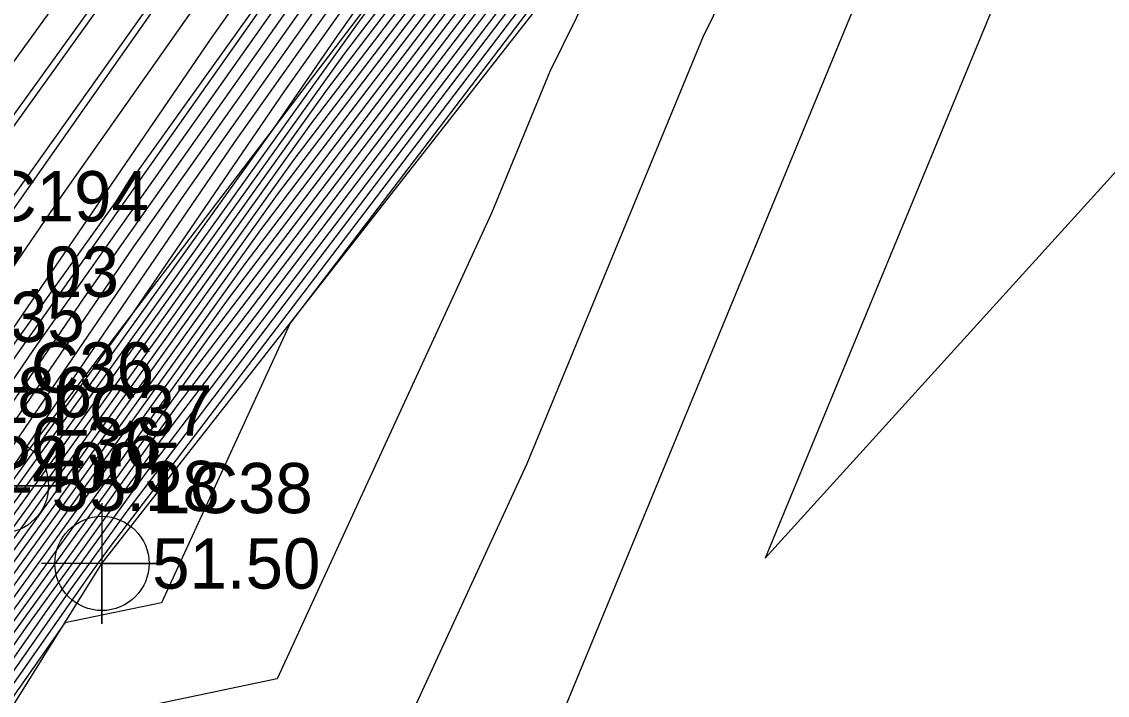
# Model space of a CAD drawing. Extents: x 2188792 to 2191981, y 386090 to 389710.
# Drawn here: x 2190065.7 to 2190119.7, y 387465.7 to 387499.2 of the extents above; entities that cross this region are included whole.
import ezdxf

# ---------------------------------------------------------------- set-up
doc = ezdxf.new("R2010")
doc.units = 0
for name, color, linetype in [('DTM Contours Major', 7, 'Continuous'), ('DTM Contours Minor', 7, 'Continuous'), ('Exist DTM Breakline', 7, 'Continuous'), ('Exist DTM Breakline Cogo Comment', 7, 'Continuous'), ('Exist DTM Breakline Cogo Elevation', 7, 'Continuous'), ('Exist DTM Breakline Cogo Number', 7, 'Continuous'), ('Exist DTM Breakline Cogo Point CELL', 7, 'Continuous'), ('Exist Roads EOP', 7, 'Continuous'), ('Exist Roads EOP Cogo Elevation', 7, 'Continuous'), ('Exist Roads EOP Cogo Number', 7, 'Continuous'), ('Exist Roads EOT', 7, 'Continuous')]:
    doc.layers.add(name, color=color, linetype=linetype)

msp = doc.modelspace()

# ---------------------------------------------------------------- linework, layer by layer
at = {"layer": 'DTM Contours Major'}
for points in [[(2189985.275, 387383.669), (2189994.24, 387397.334), (2190000.542, 387406.584), (2190005.068, 387412.932), (2190013.175, 387425.126), (2190018.833, 387434.036), (2190019.851, 387435.22), (2190023.561, 387439.509), (2190030.225, 387447.562), (2190040.144, 387460.464), (2190042.779, 387463.794), (2190047.272, 387469.736), (2190059.404, 387485.693), (2190062.073, 387489.527), (2190073.957, 387506.082), (2190075.657, 387508.517), (2190091.037, 387529.933), (2190091.267, 387530.33), (2190091.329, 387530.517), (2190091.393, 387530.607), (2190108.388, 387554.062)], [(2190106.731, 387542.448), (2190099.469, 387532.426), (2190096.508, 387528.215), (2190094.775, 387523.014), (2190093.569, 387521.301), (2190083.683, 387507.247), (2190079.859, 387502.134), (2190066.248, 387482.85), (2190062.633, 387477.566), (2190059.105, 387472.827), (2190048.491, 387458.326), (2190044.873, 387453.452), (2190030.711, 387434.1), (2190030.018, 387433.137), (2190027.341, 387429.417), (2190023.779, 387424.466), (2190009.82, 387405.068), (2190006.105, 387399.906), (2189992.299, 387380.721)], [(2190110.745, 387540.41), (2190105.891, 387533.526), (2190105.582, 387533.077), (2190100.754, 387526.228), (2190099.627, 387524.62), (2190095.823, 387519.225), (2190089.739, 387510.691), (2190082.098, 387500.475), (2190078.739, 387495.716), (2190071.019, 387484.433), (2190064.89, 387475.89), (2190054.344, 387461.328), (2190051.756, 387457.851), (2190051.243, 387457.151), (2190036.94, 387437.88), (2190033.304, 387432.912), (2190030.391, 387428.863), (2190029.739, 387427.956), (2190014.659, 387406.997), (2190012.23, 387403.623), (2189995.968, 387381.02)], [(2190114.284, 387538.324), (2190111.626, 387535.207), (2190109.01, 387531.496), (2190106.262, 387527.516), (2190103.844, 387524.086), (2190101.173, 387520.274), (2190099.676, 387517.333), (2190092.293, 387506.847), (2190085.473, 387497.899), (2190075.878, 387485.31), (2190067.614, 387473.791), (2190061.717, 387465.648), (2190054.342, 387455.145), (2190047.627, 387445.581), (2190036.85, 387430.761), (2190035.701, 387429.225), (2190033.337, 387425.963), (2190026.852, 387417.298), (2190015.609, 387401.795), (2190008.751, 387392.635)], [(2190111.185, 387537.809), (2190107.45, 387532.511), (2190105.922, 387530.297), (2190102.299, 387525.157), (2190098.297, 387519.445), (2190097.984, 387518.83), (2190086.635, 387502.712), (2190083.893, 387499.114), (2190080.036, 387494.053), (2190066.252, 387474.84), (2190056.415, 387461.258), (2190052.824, 387456.143), (2190049.554, 387451.486), (2190035.249, 387431.813), (2190034.794, 387431.205), (2190031.653, 387426.871), (2190029.033, 387423.37), (2190014.005, 387402.646), (2190010.979, 387398.605), (2189996.34, 387378.433)], [(2190115.906, 387537.107), (2190112.067, 387532.606), (2190110.569, 387530.481), (2190106.602, 387524.736), (2190105.389, 387523.015), (2190104.049, 387521.102), (2190101.368, 387515.835), (2190097.95, 387510.981), (2190087.053, 387496.683), (2190071.72, 387476.566), (2190068.976, 387472.742), (2190067.018, 387470.039), (2190055.86, 387454.147), (2190045.7, 387439.676), (2190038.452, 387429.71), (2190036.608, 387427.245), (2190035.022, 387425.056), (2190024.671, 387411.226), (2190017.214, 387400.943), (2190006.522, 387386.664)], [(2190117.527, 387535.891), (2190112.507, 387530.004), (2190112.128, 387529.466), (2190106.942, 387521.955), (2190106.934, 387521.944), (2190106.925, 387521.931), (2190106.753, 387521.593), (2190104.953, 387515.237), (2190106.299, 387512.1), (2190099.551, 387498.387), (2190090.794, 387477.182), (2190084.115, 387462.685), (2190060.634, 387457.786), (2190057.378, 387453.148), (2190043.772, 387433.771), (2190040.054, 387428.658), (2190037.515, 387425.265), (2190036.706, 387424.148), (2190022.49, 387405.154), (2190018.819, 387400.092), (2190004.294, 387380.694)]]:
    msp.add_lwpolyline(points, dxfattribs=at)
at = {"layer": 'DTM Contours Minor'}
for points in [[(2189991.5, 387387.944), (2190006.309, 387407.959), (2190009.862, 387412.875), (2190024.083, 387432.111), (2190024.846, 387433.166), (2190027.155, 387436.291), (2190041.613, 387456.61), (2190044.615, 387460.675), (2190057.101, 387478.28), (2190058.7, 387480.441), (2190060.418, 387482.951), (2190075.921, 387505.01), (2190076.691, 387506.131), (2190089.632, 387524.531), (2190091.732, 387528.156), (2190092.365, 387530.057), (2190093.008, 387530.971), (2190108.057, 387551.739)], [(2189998.486, 387394.909), (2190007.419, 387406.982), (2190016.684, 387419.801), (2190025.109, 387431.197), (2190026.917, 387433.7), (2190028.281, 387435.545), (2190036.815, 387447.54), (2190045.891, 387459.829), (2190052.965, 387469.804), (2190060.087, 387479.431), (2190067.74, 387490.608), (2190077.205, 387504.075), (2190082.418, 387511.662), (2190090.831, 387523.625), (2190092.196, 387525.982), (2190093.401, 387529.596), (2190094.623, 387531.335), (2190107.725, 387549.417)], [(2189990.911, 387381.736), (2190005.473, 387401.874), (2190008.529, 387406.005), (2190023.505, 387426.727), (2190026.134, 387430.283), (2190028.989, 387434.234), (2190029.406, 387434.799), (2190032.018, 387438.47), (2190047.166, 387458.984), (2190048.83, 387461.329), (2190061.474, 387478.421), (2190075.063, 387498.265), (2190078.489, 387503.14), (2190088.144, 387517.193), (2190092.031, 387522.719), (2190092.661, 387523.808), (2190094.437, 387529.136), (2190096.239, 387531.699), (2190107.394, 387547.094)], [(2190107.063, 387544.771), (2190097.854, 387532.062), (2190095.472, 387528.675), (2190093.273, 387522.075), (2190093.123, 387521.862), (2190080.566, 387504.01), (2190079.411, 387502.466), (2190063.75, 387480.277), (2190062.143, 387477.929), (2190060.575, 387475.822), (2190047.94, 387458.561), (2190046.46, 387456.566), (2190030.192, 387434.337), (2190029.944, 387433.992), (2190026.861, 387429.709), (2190025.602, 387427.959), (2190009.337, 387405.358), (2190008.133, 387403.683), (2189991.814, 387381.006)], [(2190110.657, 387540.931), (2190105.579, 387533.729), (2190105.514, 387533.633), (2190100.445, 387526.443), (2190100.195, 387526.086), (2190095.357, 387519.224), (2190093.956, 387517.258), (2190081.65, 387500.807), (2190076.24, 387493.143), (2190064.592, 387476.117), (2190053.226, 387460.846), (2190050.693, 387457.386), (2190038.527, 387440.994), (2190032.785, 387433.149), (2190030.317, 387429.718), (2190029.259, 387428.248), (2190016.483, 387410.491), (2190011.748, 387403.912), (2189997.995, 387384.797)], [(2190106.4, 387540.126), (2190101.085, 387532.79), (2190097.544, 387527.754), (2190096.277, 387523.953), (2190094.014, 387520.74), (2190086.8, 387510.483), (2190080.306, 387501.803), (2190068.746, 387485.423), (2190063.122, 387477.204), (2190057.635, 387469.832), (2190049.041, 387458.091), (2190043.287, 387450.338), (2190031.229, 387433.862), (2190030.093, 387432.282), (2190027.82, 387429.125), (2190021.955, 387420.972), (2190010.302, 387404.779), (2190004.078, 387396.129), (2189992.784, 387380.435)], [(2190110.833, 387539.89), (2190106.203, 387533.323), (2190105.65, 387532.521), (2190101.063, 387526.014), (2190099.059, 387523.154), (2190096.289, 387519.225), (2190085.523, 387504.124), (2190082.546, 387500.144), (2190081.237, 387498.289), (2190078.229, 387493.893), (2190065.162, 387475.68), (2190052.174, 387457.746), (2190051.61, 387456.942), (2190051.096, 387456.21), (2190042.68, 387444.636), (2190035.353, 387434.765), (2190033.823, 387432.674), (2190030.466, 387428.008), (2190030.218, 387427.664), (2190012.835, 387403.503), (2190012.712, 387403.333), (2190011.047, 387401.019), (2189995.118, 387379.07)], [(2190110.921, 387539.37), (2190106.515, 387533.12), (2190105.718, 387531.965), (2190101.372, 387525.8), (2190098.49, 387521.687), (2190096.755, 387519.226), (2190085.439, 387503.353), (2190083.241, 387500.231), (2190082.946, 387499.844), (2190082.531, 387499.299), (2190065.435, 387475.47), (2190053.235, 387458.624), (2190051.913, 387456.742), (2190050.71, 387455.029), (2190034.287, 387432.444), (2190034.25, 387432.393), (2190030.642, 387427.415), (2190030.342, 387427.014), (2190013.042, 387403.157), (2190012.316, 387402.187), (2189995.424, 387378.911)], [(2190111.009, 387538.849), (2190106.827, 387532.917), (2190105.786, 387531.409), (2190101.681, 387525.586), (2190097.922, 387520.221), (2190097.221, 387519.226), (2190092.649, 387512.813), (2190084.372, 387501.058), (2190083.262, 387499.601), (2190081.699, 387497.551), (2190065.707, 387475.26), (2190054.295, 387459.502), (2190052.217, 387456.543), (2190050.325, 387453.848), (2190034.608, 387432.234), (2190034.431, 387431.997), (2190030.979, 387427.234), (2190029.906, 387425.799), (2190013.363, 387402.987), (2190011.87, 387400.993), (2189995.729, 387378.751)], [(2190111.097, 387538.329), (2190107.139, 387532.714), (2190105.854, 387530.853), (2190101.99, 387525.371), (2190097.722, 387519.28), (2190097.646, 387519.13), (2190085.504, 387501.885), (2190083.578, 387499.358), (2190080.867, 387495.802), (2190065.979, 387475.05), (2190055.355, 387460.38), (2190052.52, 387456.343), (2190049.939, 387452.667), (2190034.928, 387432.023), (2190034.612, 387431.601), (2190031.316, 387427.052), (2190029.469, 387424.585), (2190013.684, 387402.816), (2190011.424, 387399.799), (2189996.034, 387378.592)], [(2190114.608, 387538.081), (2190111.714, 387534.687), (2190109.321, 387531.293), (2190106.33, 387526.96), (2190104.153, 387523.872), (2190101.748, 387520.44), (2190100.015, 387517.033), (2190093.424, 387507.674), (2190085.789, 387497.656), (2190075.046, 387483.561), (2190067.886, 387473.581), (2190062.777, 387466.526), (2190054.645, 387454.945), (2190047.241, 387444.4), (2190037.171, 387430.551), (2190035.882, 387428.829), (2190033.674, 387425.782), (2190026.416, 387416.084), (2190015.93, 387401.624), (2190008.305, 387391.441)], [(2190106.069, 387537.803), (2190102.7, 387533.154), (2190098.58, 387527.294), (2190097.779, 387524.892), (2190094.46, 387520.178), (2190089.917, 387513.72), (2190080.754, 387501.471), (2190071.244, 387487.996), (2190063.612, 387476.842), (2190056.166, 387466.837), (2190049.592, 387457.856), (2190041.7, 387447.223), (2190031.748, 387433.624), (2190030.167, 387431.428), (2190028.3, 387428.833), (2190020.131, 387417.478), (2190010.784, 387404.49), (2190002.05, 387392.352)], [(2190115.257, 387537.594), (2190111.89, 387533.646), (2190109.945, 387530.887), (2190106.466, 387525.848), (2190104.771, 387523.443), (2190102.899, 387520.771), (2190100.691, 387516.434), (2190095.687, 387509.327), (2190086.421, 387497.169), (2190073.383, 387480.063), (2190068.431, 387473.162), (2190064.898, 387468.283), (2190055.253, 387454.546), (2190046.47, 387442.038), (2190037.812, 387430.13), (2190036.245, 387428.037), (2190034.348, 387425.419), (2190025.544, 387413.655), (2190016.572, 387401.284), (2190007.414, 387389.052)], [(2190114.933, 387537.837), (2190111.802, 387534.167), (2190109.633, 387531.09), (2190106.398, 387526.404), (2190104.462, 387523.658), (2190102.324, 387520.605), (2190100.353, 387516.734), (2190094.556, 387508.5), (2190086.105, 387497.413), (2190074.214, 387481.812), (2190068.159, 387473.371), (2190063.837, 387467.405), (2190054.949, 387454.746), (2190046.856, 387443.219), (2190037.491, 387430.341), (2190036.064, 387428.433), (2190034.011, 387425.6), (2190025.98, 387414.869), (2190016.251, 387401.454), (2190007.859, 387390.247)], [(2190111.274, 387537.288), (2190107.762, 387532.308), (2190105.99, 387529.741), (2190102.608, 387524.943), (2190098.873, 387519.611), (2190098.323, 387518.531), (2190087.767, 387503.539), (2190084.209, 387498.871), (2190079.204, 387492.304), (2190066.524, 387474.631), (2190057.476, 387462.136), (2190053.128, 387455.944), (2190049.168, 387450.305), (2190035.569, 387431.603), (2190034.975, 387430.809), (2190031.99, 387426.689), (2190028.597, 387422.156), (2190014.326, 387402.476), (2190010.533, 387397.411), (2189996.645, 387378.274)], [(2190115.581, 387537.351), (2190111.979, 387533.126), (2190110.257, 387530.684), (2190106.534, 387525.292), (2190105.08, 387523.229), (2190103.474, 387520.937), (2190101.03, 387516.135), (2190096.819, 387510.154), (2190086.737, 387496.926), (2190072.551, 387478.315), (2190068.704, 387472.952), (2190065.958, 387469.161), (2190055.556, 387454.346), (2190046.085, 387440.857), (2190038.132, 387429.92), (2190036.426, 387427.641), (2190034.685, 387425.237), (2190025.107, 387412.441), (2190016.893, 387401.114), (2190006.968, 387387.858)], [(2190111.362, 387536.768), (2190108.074, 387532.105), (2190106.058, 387529.185), (2190102.917, 387524.729), (2190099.448, 387519.777), (2190098.661, 387518.231), (2190088.898, 387504.366), (2190084.525, 387498.628), (2190078.373, 387490.556), (2190066.797, 387474.421), (2190058.536, 387463.014), (2190053.431, 387455.744), (2190048.783, 387449.124), (2190035.889, 387431.392), (2190035.157, 387430.413), (2190032.327, 387426.508), (2190028.161, 387420.942), (2190014.647, 387402.305), (2190010.087, 387396.217), (2189996.95, 387378.115)], [(2190116.554, 387536.621), (2190112.243, 387531.565), (2190111.192, 387530.075), (2190106.738, 387523.624), (2190106.007, 387522.586), (2190105.2, 387521.434), (2190102.045, 387515.236), (2190100.213, 387512.635), (2190087.684, 387496.197), (2190070.056, 387473.069), (2190069.521, 387472.322), (2190069.139, 387471.795), (2190056.467, 387453.747), (2190044.929, 387437.314), (2190039.093, 387429.289), (2190036.971, 387426.453), (2190035.695, 387424.693), (2190023.799, 387408.797), (2190017.856, 387400.603), (2190005.631, 387384.276)], [(2190116.23, 387536.864), (2190112.155, 387532.085), (2190110.88, 387530.278), (2190106.67, 387524.18), (2190105.698, 387522.801), (2190104.624, 387521.268), (2190101.706, 387515.536), (2190099.082, 387511.808), (2190087.368, 387496.44), (2190070.888, 387474.817), (2190069.248, 387472.532), (2190068.078, 387470.917), (2190056.163, 387453.947), (2190045.314, 387438.495), (2190038.773, 387429.499), (2190036.789, 387426.849), (2190035.358, 387424.874), (2190024.235, 387410.012), (2190017.535, 387400.773), (2190006.077, 387385.47)], [(2190117.203, 387536.134), (2190112.419, 387530.525), (2190111.816, 387529.669), (2190106.874, 387522.511), (2190106.625, 387522.158), (2190106.35, 387521.765), (2190102.721, 387514.637), (2190102.476, 387514.289), (2190097.206, 387507.375), (2190091.943, 387496.681), (2190089.034, 387489.636), (2190078.365, 387466.477), (2190064.22, 387463.525), (2190057.074, 387453.348), (2190044.158, 387434.952), (2190039.734, 387428.868), (2190037.333, 387425.661), (2190036.369, 387424.33), (2190022.926, 387406.369), (2190018.498, 387400.262), (2190004.74, 387381.888)], [(2190116.879, 387536.377), (2190112.331, 387531.045), (2190111.504, 387529.872), (2190106.806, 387523.067), (2190106.316, 387522.372), (2190105.775, 387521.599), (2190102.383, 387514.937), (2190101.345, 387513.462), (2190088, 387495.954), (2190079.019, 387484.171), (2190072.614, 387470.268), (2190067.806, 387469.265), (2190056.77, 387453.548), (2190044.543, 387436.133), (2190039.413, 387429.079), (2190037.152, 387426.057), (2190036.032, 387424.511), (2190023.362, 387407.583), (2190018.177, 387400.433), (2190005.185, 387383.082)], [(2190111.45, 387536.248), (2190108.386, 387531.902), (2190106.126, 387528.628), (2190103.226, 387524.514), (2190100.023, 387519.943), (2190098.999, 387517.932), (2190090.03, 387505.193), (2190084.841, 387498.385), (2190077.541, 387488.807), (2190067.069, 387474.211), (2190059.596, 387463.892), (2190053.735, 387455.544), (2190048.398, 387447.943), (2190036.21, 387431.182), (2190035.338, 387430.017), (2190032.664, 387426.326), (2190027.725, 387419.727), (2190014.968, 387402.135), (2190009.642, 387395.023)], [(2190105.738, 387535.48), (2190104.315, 387533.517), (2190099.616, 387526.833), (2190099.282, 387525.831), (2190094.906, 387519.617), (2190093.034, 387516.956), (2190081.202, 387501.139), (2190073.742, 387490.57), (2190064.102, 387476.479), (2190054.696, 387463.842), (2190050.142, 387457.621), (2190040.113, 387444.109), (2190032.267, 387433.387), (2190030.242, 387430.573), (2190028.78, 387428.54), (2190018.307, 387413.985), (2190011.266, 387404.201), (2190000.023, 387388.574)], [(2190117.852, 387535.647), (2190112.595, 387529.484), (2190112.44, 387529.263), (2190110.263, 387526.111), (2190109.543, 387521.58), (2190108.03, 387516.24), (2190111.326, 387508.562), (2190107.159, 387500.094), (2190092.553, 387464.728), (2190089.865, 387458.894), (2190064.663, 387453.635), (2190057.974, 387451.949), (2190057.323, 387452.317), (2190057.048, 387452.046), (2190043.387, 387432.59), (2190040.375, 387428.448), (2190037.696, 387424.869), (2190037.043, 387423.967), (2190022.054, 387403.94), (2190019.14, 387399.922), (2190003.848, 387379.5)], [(2190111.538, 387535.728), (2190108.698, 387531.699), (2190106.194, 387528.072), (2190103.535, 387524.3), (2190100.598, 387520.108), (2190099.338, 387517.632), (2190091.161, 387506.02), (2190085.157, 387498.142), (2190076.709, 387487.058), (2190067.341, 387474.001), (2190060.657, 387464.77), (2190054.038, 387455.345), (2190048.012, 387446.762), (2190036.53, 387430.972), (2190035.519, 387429.621), (2190033, 387426.145), (2190027.288, 387418.513), (2190015.288, 387401.965), (2190009.196, 387393.829)], [(2190120.233, 387534.548), (2190118.327, 387532.958), (2190113.354, 387528.27), (2190112.232, 387521.211), (2190111.108, 387517.242), (2190116.352, 387505.024), (2190114.766, 387501.801), (2190102.656, 387472.478), (2190127.28, 387499.605)]]:
    msp.add_lwpolyline(points, dxfattribs=at)
at = {"layer": 'Exist DTM Breakline'}
for points in [[(2189987.902, 387384.357), (2190026.315, 387436.848), (2190058.298, 387480.734), (2190089.535, 387524.604)], [(2189991.613, 387381.125), (2190029.902, 387434.47), (2190061.751, 387478.219), (2190093.06, 387521.942)], [(2189994.964, 387379.15), (2190034.2, 387432.501), (2190064.649, 387476.075), (2190097.537, 387519.226)], [(2190002.292, 387375.33), (2190041.742, 387427.55), (2190069.653, 387472.22), (2190102.826, 387514.545)]]:
    msp.add_lwpolyline(points, dxfattribs=at)
at = {"layer": 'Exist DTM Breakline Cogo Point CELL'}
for points in [[(2190064.649, 387479.075), (2190064.649, 387473.075), (2190064.649, 387476.075), (2190067.649, 387476.075), (2190061.649, 387476.075)], [(2190069.653, 387475.22), (2190069.653, 387469.22), (2190069.653, 387472.22), (2190072.653, 387472.22), (2190066.653, 387472.22)]]:
    msp.add_lwpolyline(points, dxfattribs=at)
for centre in [(2190064.649, 387476.075), (2190069.653, 387472.22)]:
    msp.add_circle(centre, 2.344, dxfattribs=at)
at = {"layer": 'Exist Roads EOP'}
msp.add_lwpolyline([(2190335.128, 387868.989), (2190306.373, 387829.271), (2190274.581, 387784.921), (2190245.133, 387744.071), (2190214.553, 387701.741), (2190184.89, 387660.475), (2190157.493, 387622.204), (2190126.048, 387578.501), (2190091.216, 387530.568), (2190059.634, 387486.726), (2190026.932, 387441.783), (2189997.689, 387401.032), (2189957.023, 387344.154), (2189927.908, 387303.922), (2189889.008, 387250.224), (2189856.606, 387205.5), (2189825.68, 387162.612), (2189795.668, 387120.822), (2189765.955, 387079.619), (2189734.998, 387036.704), (2189703.849, 386993.356), (2189673.984, 386951.979), (2189643.253, 386909.427)], dxfattribs=at)
at = {"layer": 'Exist Roads EOT'}
msp.add_lwpolyline([(2190333.162, 387868.755), (2190301.785, 387825.12), (2190269.645, 387780.315), (2190237.827, 387736.49), (2190205.816, 387692.275), (2190173.845, 387647.822), (2190143.211, 387605.324), (2190112.772, 387563.076), (2190082.117, 387520.492), (2190050.947, 387477.405), (2190019.959, 387434.524), (2189989.253, 387391.986)], dxfattribs=at)

# ---------------------------------------------------------------- texts
at = {"layer": 'Exist DTM Breakline Cogo Comment'}
msp.add_text('*BL4005', height=2.5, dxfattribs=at).set_placement((2190060.798, 387475.734))
at = {"layer": 'Exist DTM Breakline Cogo Elevation'}
for s, p in [('56.86', (2190060.798, 387479.484)), ('56.36', (2190064.251, 387476.969)), ('55.18', (2190067.149, 387474.825)), ('51.50', (2190072.153, 387470.97))]:
    msp.add_text(s, height=2.5, dxfattribs=at).set_placement(p)
at = {"layer": 'Exist DTM Breakline Cogo Number'}
for s, p in [('LC35', (2190060.798, 387483.234)), ('LC36', (2190064.251, 387480.719)), ('LC37', (2190067.149, 387478.575)), ('LC38', (2190072.153, 387474.72))]:
    msp.add_text(s, height=2.5, dxfattribs=at).set_placement(p)
at = {"layer": 'Exist Roads EOP Cogo Elevation'}
msp.add_text('57.03', height=2.5, dxfattribs=at).set_placement((2190062.134, 387485.476))
at = {"layer": 'Exist Roads EOP Cogo Number'}
msp.add_text('LC194', height=2.5, dxfattribs=at).set_placement((2190062.134, 387489.226))

doc.saveas('drawing.dxf')
